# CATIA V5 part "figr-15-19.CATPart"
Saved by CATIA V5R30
Part number: Part1
Bounding box of the stored display mesh (mm): x -46.56 to 46.56, y -36.965 to 25.965, z 0 to 40
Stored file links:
  D:\PROJECTS\CATIA V56R 2020\Resources\Parts File\c15_catia_v5_6r2020_prt\figr-15-19.CATPart
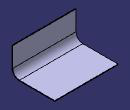
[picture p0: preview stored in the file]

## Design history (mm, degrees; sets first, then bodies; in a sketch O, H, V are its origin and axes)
SheetMetalParameters1: Thickness 1, BendRadius 1, KFactor 0.325257 {= log(min(100,max(20*SheetMetalParameters1.BendRadius,SheetMetalParameters1.Thickness)/SheetMetalParameters1.Thickness))/log(100)/2}, ReliefRadialLength 1, ReliefAxialLength 2, MinimumBendRadius 0
Body1 (main body)
  Sketch1 on xy-plane, origin (0, 0, 0), H (1, 0, 0), V (0, 1, 0)
    line L1 (-46.5596, 25.9646) -> (46.5596, 25.9646)
    line L2 (46.5596, 25.9646) -> (46.5596, -25.9646)
    line L3 (46.5596, -25.9646) -> (-46.5596, -25.9646)
    line L4 (-46.5596, -25.9646) -> (-46.5596, 25.9646)
    horizontal: L1 H, L3 H
    vertical: L2 V, L4 V
    symmetry: L1 L3 H, L4 L2 V
  Wall1: Thickness 1, Profile Sketch1
  d_NewWallOnEdge1: NewWallOnEdge_Edge edge [face of Wall1 | face of Wall1], NewWallOnEdge_Length 40, NewWallOnEdge_HeightLimitOffset 0, NewWallOnEdge_WidthOffset1 0, NewWallOnEdge_WidthOffset2 0, NewWallOnEdge_Angle 90, NewWallOnEdge_BendRadiusValue 10 {= d_NewWallOnEdge1.Clearance}, NewWallOnEdge_BendTable SheetMetalParameters1, KFacteur 0.5 {= log(min(100,max(20*d_NewWallOnEdge1.Radius,SheetMetalParameters1.Thickness)/SheetMetalParameters1.Thickness))/log(100)/2}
